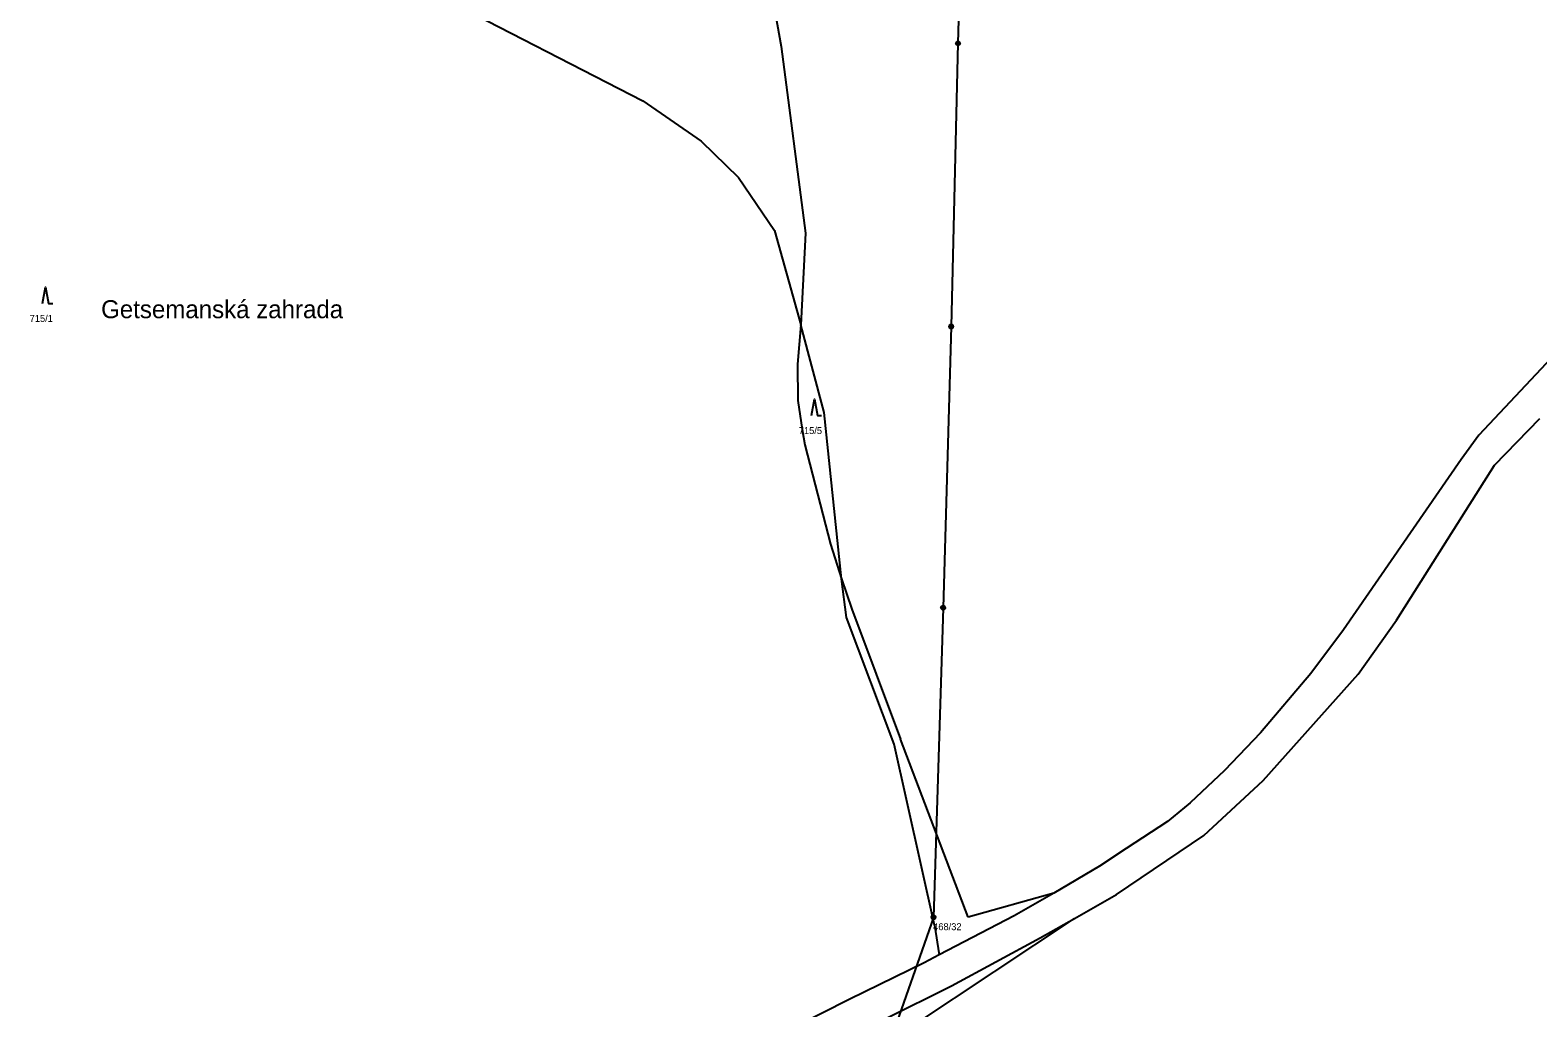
# Model space of a CAD drawing. Extents: x -852001 to -842497, y -1063614 to -1052182.
# Drawn here: x -845332.6 to -844963.9, y -1062421 to -1062182 of the extents above; entities that cross this region are included whole.
import ezdxf

# ---------------------------------------------------------------- set-up
doc = ezdxf.new("R2010")
doc.units = 0
for name, color, linetype in [('Default', 7, 'Continuous'), ('KN_HRANICE', 7, 'Continuous'), ('KN_KULTURY', 7, 'Continuous'), ('KN_PARCELY', 7, 'Continuous'), ('KN_VEDENI', 7, 'Continuous')]:
    doc.layers.add(name, color=color, linetype=linetype)

# ---------------------------------------------------------------- blocks, each defined once
blk = doc.blocks.new('308')
at = {"layer": 'Default'}
blk.add_lwpolyline([(-0.75, 0), (0, 4), (0.75, 0), (1.75, 0)], dxfattribs=at)
blk = doc.blocks.new('601')
at = {"layer": 'Default'}
blk.add_lwpolyline([(-0.15, 0.48), (0.16, 0.48), (0.41, 0.3), (0.51, 0.01), (0.41, -0.28), (0.16, -0.46), (-0.15, -0.46), (-0.4, -0.28), (-0.5, 0.01), (-0.4, 0.3), (-0.15, 0.48), (-0.12, 0.44), (0.12, 0.44), (0.28, 0.36), (-0.28, 0.36), (-0.36, 0.28), (0.36, 0.28), (0.36, 0.2), (-0.36, 0.2), (-0.4, 0.12), (0.4, 0.12), (0.44, 0.04), (-0.44, 0.04), (-0.44, -0.04), (0.44, -0.04), (0.41, -0.12), (-0.4, -0.12), (-0.39, -0.2), (0.42, -0.2), (0.37, -0.28), (-0.35, -0.28), (-0.27, -0.36), (0.29, -0.36), (0.18, -0.44), (-0.16, -0.44)], dxfattribs=at)

msp = doc.modelspace()

# ---------------------------------------------------------------- linework, layer by layer
at = {"layer": 'KN_HRANICE'}
for p, q in [((-845265.26, -1062156.82), (-845182.76, -1062199.3)), ((-845265.26, -1062156.82), (-845182.76, -1062199.3)), ((-845153.37, -1062160.62), (-845148.98, -1062185.97)), ((-845153.37, -1062160.62), (-845148.98, -1062185.97)), ((-845148.98, -1062185.97), (-845143.01, -1062231.6)), ((-845148.98, -1062185.97), (-845143.01, -1062231.6)), ((-845182.76, -1062199.3), (-845168.53, -1062209.15)), ((-845182.76, -1062199.3), (-845168.53, -1062209.15)), ((-845168.53, -1062209.15), (-845159.37, -1062218.05)), ((-845168.53, -1062209.15), (-845159.37, -1062218.05)), ((-845159.37, -1062218.05), (-845150.62, -1062230.97)), ((-845159.37, -1062218.05), (-845150.62, -1062230.97)), ((-845150.62, -1062230.97), (-845144.14, -1062254.07)), ((-845150.62, -1062230.97), (-845144.14, -1062254.07)), ((-845143.01, -1062231.6), (-845144.14, -1062254.07)), ((-845143.01, -1062231.6), (-845144.14, -1062254.07)), ((-845144.14, -1062254.07), (-845144.97, -1062263.63)), ((-845144.14, -1062254.07), (-845144.97, -1062263.63)), ((-845138.4, -1062275.48), (-845144.14, -1062254.07)), ((-845138.4, -1062275.48), (-845144.14, -1062254.07)), ((-844952.53, -1062253.59), (-844978.34, -1062281.01)), ((-844952.53, -1062253.59), (-844978.34, -1062281.01)), ((-845144.97, -1062263.63), (-845144.84, -1062272.5)), ((-845144.97, -1062263.63), (-845144.84, -1062272.5)), ((-845144.84, -1062272.5), (-845143.83, -1062279.65)), ((-845144.84, -1062272.5), (-845143.83, -1062279.65)), ((-845134.22, -1062316.16), (-845138.4, -1062275.48)), ((-845134.22, -1062316.16), (-845138.4, -1062275.48)), ((-844974.5, -1062288.35), (-844963.4, -1062276.91)), ((-844974.5, -1062288.35), (-844963.4, -1062276.91)), ((-845143.83, -1062279.65), (-845143.13, -1062283.35)), ((-845143.83, -1062279.65), (-845143.13, -1062283.35)), ((-844978.34, -1062281.01), (-844982.61, -1062286.96)), ((-844978.34, -1062281.01), (-844982.61, -1062286.96)), ((-845143.13, -1062283.35), (-845136.91, -1062307.66)), ((-845143.13, -1062283.35), (-845136.91, -1062307.66)), ((-844982.61, -1062286.96), (-845011.44, -1062328.57)), ((-844982.61, -1062286.96), (-845011.44, -1062328.57)), ((-844998.41, -1062326.27), (-844974.5, -1062288.35)), ((-844998.41, -1062326.27), (-844974.5, -1062288.35)), ((-845136.91, -1062307.66), (-845134.22, -1062316.16)), ((-845136.91, -1062307.66), (-845134.22, -1062316.16)), ((-845134.22, -1062316.16), (-845131.69, -1062323.54)), ((-845132.97, -1062325.6), (-845134.22, -1062316.16)), ((-845134.22, -1062316.16), (-845131.69, -1062323.54)), ((-845132.97, -1062325.6), (-845134.22, -1062316.16)), ((-845121.27, -1062356.56), (-845132.97, -1062325.6)), ((-845121.27, -1062356.56), (-845132.97, -1062325.6)), ((-845131.69, -1062323.54), (-845119.75, -1062355.31)), ((-845131.69, -1062323.54), (-845119.75, -1062355.31)), ((-845007.83, -1062339.43), (-844998.41, -1062326.27)), ((-845007.83, -1062339.43), (-844998.41, -1062326.27)), ((-845011.44, -1062328.57), (-845019.42, -1062339.3)), ((-845011.44, -1062328.57), (-845019.42, -1062339.3)), ((-845019.42, -1062339.3), (-845031.74, -1062353.78)), ((-845019.42, -1062339.3), (-845031.74, -1062353.78)), ((-845031.03, -1062365.42), (-845007.83, -1062339.43)), ((-845031.03, -1062365.42), (-845007.83, -1062339.43)), ((-845103.22, -1062398.82), (-845119.75, -1062355.31)), ((-845103.22, -1062398.82), (-845119.75, -1062355.31)), ((-845031.74, -1062353.78), (-845040.53, -1062363)), ((-845031.74, -1062353.78), (-845040.53, -1062363)), ((-845111.47, -1062400.8), (-845121.27, -1062356.56)), ((-845111.47, -1062400.8), (-845121.27, -1062356.56)), ((-845040.53, -1062363), (-845048.89, -1062370.93)), ((-845040.53, -1062363), (-845048.89, -1062370.93)), ((-845045.55, -1062378.92), (-845031.03, -1062365.42)), ((-845045.55, -1062378.92), (-845031.03, -1062365.42)), ((-845048.89, -1062370.93), (-845054.46, -1062375.44)), ((-845048.89, -1062370.93), (-845054.46, -1062375.44)), ((-845054.46, -1062375.44), (-845064.54, -1062382.09)), ((-845054.46, -1062375.44), (-845064.54, -1062382.09)), ((-845064.54, -1062382.09), (-845071.07, -1062386.38)), ((-845064.54, -1062382.09), (-845071.07, -1062386.38)), ((-845066.89, -1062393.3), (-845045.55, -1062378.92)), ((-845066.89, -1062393.3), (-845045.55, -1062378.92)), ((-845071.07, -1062386.38), (-845082.22, -1062393.02)), ((-845071.07, -1062386.38), (-845082.22, -1062393.02)), ((-845082.22, -1062393.02), (-845103.22, -1062398.82)), ((-845082.22, -1062393.02), (-845103.22, -1062398.82)), ((-845082.22, -1062393.02), (-845091.93, -1062398.54)), ((-845082.22, -1062393.02), (-845091.93, -1062398.54)), ((-845077.21, -1062399.17), (-845066.89, -1062393.3)), ((-845077.21, -1062399.17), (-845066.89, -1062393.3)), ((-845116.54, -1062425.24), (-845077.21, -1062399.17)), ((-845116.54, -1062425.24), (-845077.21, -1062399.17)), ((-845091.93, -1062398.54), (-845110.3, -1062408.08)), ((-845091.93, -1062398.54), (-845110.3, -1062408.08)), ((-845085.56, -1062403.91), (-845077.21, -1062399.17)), ((-845085.56, -1062403.91), (-845077.21, -1062399.17)), ((-845111.47, -1062400.8), (-845110.3, -1062408.08)), ((-845111.47, -1062400.8), (-845110.3, -1062408.08)), ((-845107.28, -1062415.63), (-845085.56, -1062403.91)), ((-845107.28, -1062415.63), (-845085.56, -1062403.91)), ((-845110.3, -1062408.08), (-845114.01, -1062410.01)), ((-845110.3, -1062408.08), (-845114.01, -1062410.01)), ((-845114.01, -1062410.01), (-845132.19, -1062418.9)), ((-845114.01, -1062410.01), (-845132.19, -1062418.9)), ((-845132.19, -1062418.9), (-845154.67, -1062430.25)), ((-845132.19, -1062418.9), (-845154.67, -1062430.25)), ((-845123.64, -1062423.77), (-845107.28, -1062415.63)), ((-845123.64, -1062423.77), (-845107.28, -1062415.63))]:
    msp.add_line(p, q, dxfattribs=at)
at = {"layer": 'KN_VEDENI'}
for p, q in [((-845103.85, -1062109.44), (-845105.7, -1062185.21)), ((-845103.85, -1062109.44), (-845105.7, -1062185.21)), ((-845105.7, -1062185.21), (-845107.35, -1062254.46)), ((-845105.7, -1062185.21), (-845107.35, -1062254.46)), ((-845107.35, -1062254.46), (-845109.36, -1062323.23)), ((-845107.35, -1062254.46), (-845109.36, -1062323.23)), ((-845109.36, -1062323.23), (-845111.68, -1062398.9)), ((-845109.36, -1062323.23), (-845111.68, -1062398.9)), ((-845111.68, -1062398.9), (-845127.08, -1062442.66)), ((-845111.68, -1062398.9), (-845127.08, -1062442.66))]:
    msp.add_line(p, q, dxfattribs=at)

# ---------------------------------------------------------------- block references
at = {"layer": 'KN_KULTURY'}
for p in [(-845328.88, -1062248.81), (-845328.88, -1062248.81), (-845140.8, -1062276.19), (-845140.8, -1062276.19)]:
    msp.add_blockref('308', p, dxfattribs=at)
at = {"layer": 'KN_VEDENI'}
for p in [(-845105.7, -1062185.21), (-845105.7, -1062185.21), (-845107.35, -1062254.46), (-845107.35, -1062254.46), (-845109.36, -1062323.23), (-845109.36, -1062323.23), (-845111.68, -1062398.9), (-845111.68, -1062398.9)]:
    msp.add_blockref('601', p, dxfattribs=at)

# ---------------------------------------------------------------- texts
at = {"layer": 'KN_PARCELY'}
for s, height, p in [('Getsemanská zahrada', 4.4, (-845315.29, -1062252.42)), ('Getsemanská zahrada', 4.4, (-845315.29, -1062252.42)), ('715/1', 1.7, (-845332.77, -1062253.32)), ('715/1', 1.7, (-845332.77, -1062253.32)), ('715/5', 1.7, (-845144.64, -1062280.74)), ('715/5', 1.7, (-845144.64, -1062280.74)), ('468/32', 1.7, (-845111.78, -1062402.04)), ('468/32', 1.7, (-845111.78, -1062402.04))]:
    msp.add_text(s, height=height, dxfattribs=at).set_placement(p)

doc.saveas('drawing.dxf')
